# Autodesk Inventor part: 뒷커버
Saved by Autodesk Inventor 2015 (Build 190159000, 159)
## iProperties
Created: 2025-06
Part Number: 뒷커버
Material: 일반
Document SubType Name: Modeling
Designer: 104
Density: 1 g/cm^3
Appearance: 기본값
Author: 104
Author: jhkim
Creation Date: 2025-05-23
Sending System: Autodesk Inventor 2026
Preprocessor: ST-DEVELOPER v20.1
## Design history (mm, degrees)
node "뒷커버1"
node "솔리드1"
node "기준1"
